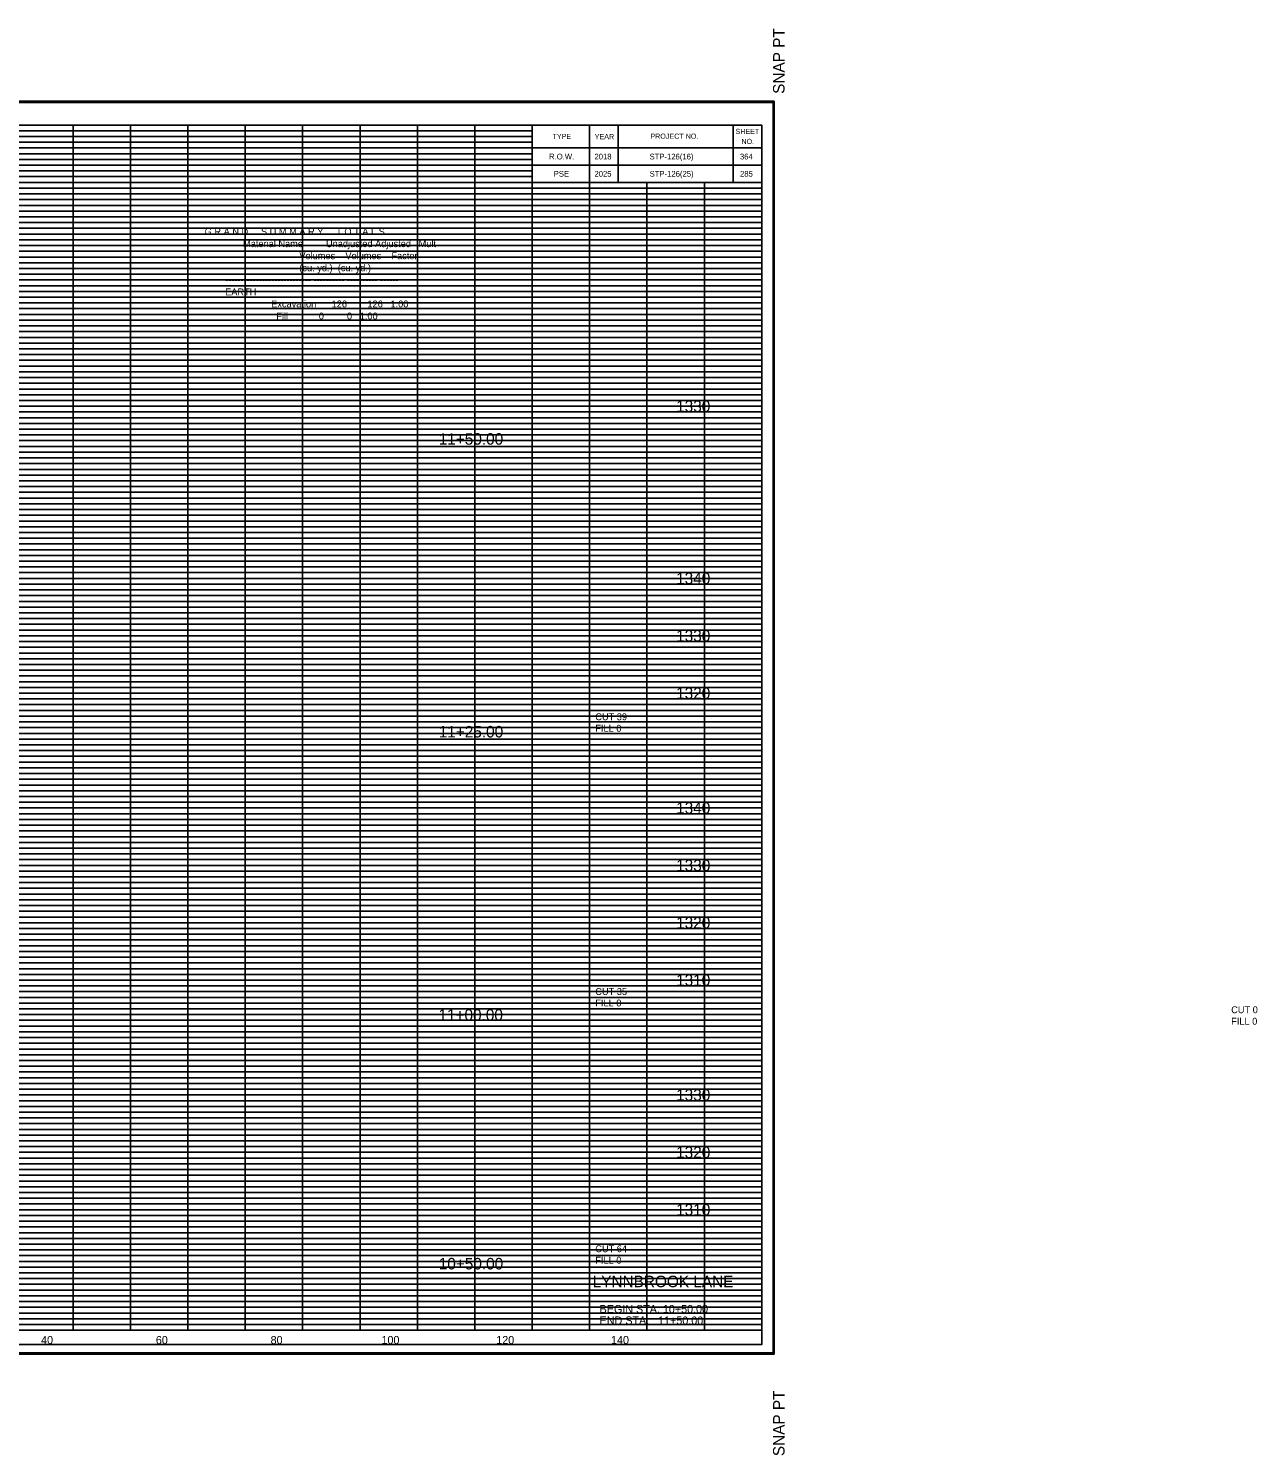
# Model space of a CAD drawing. Extents: x 980 to 1406, y 978 to 1227.
# Drawn here: x 1192.2 to 1406.4, y 978.2 to 1226.8 of the extents above; entities that cross this region are included whole.
import ezdxf

# ---------------------------------------------------------------- set-up
doc = ezdxf.new("R2010")
doc.units = 0
for name, color, linetype in [('DESIGN - SCRATCH - User 1', 7, 'Continuous'), ('DESIGN - SHEET - Corner Text', 7, 'Continuous'), ('DESIGN - SHEET - Light Grid', 7, 'Continuous'), ('DESIGN - SHEET - Linework', 7, 'Continuous'), ('DESIGN - SHEET - Plot Shape', 7, 'Continuous'), ('DESIGN - TYPICAL - Text', 7, 'Continuous')]:
    doc.layers.add(name, color=color, linetype=linetype)

# ---------------------------------------------------------------- blocks, each defined once
blk = doc.blocks.new('XSTSHT')
at = {"layer": 'DESIGN - SCRATCH - User 1'}
for p, q in [((28.5, 20.45), (28.5, 20.45)), ((29.24, 20.45), (29.24, 20.45)), ((30.49, 20.45), (30.49, 20.45)), ((31.74, 20.45), (31.74, 20.45)), ((28.5, 20.15), (28.5, 20.15)), ((29.24, 20.15), (29.24, 20.15)), ((30.49, 20.15), (30.49, 20.15)), ((31.74, 20.15), (31.74, 20.15))]:
    blk.add_line(p, q, dxfattribs=at)
at = {"layer": 'DESIGN - SHEET - Light Grid'}
for p, q in [((16, 20.9), (24, 20.9)), ((24, 20.9), (28, 20.9)), ((16, 20.8), (24, 20.8)), ((16, 20.7), (24, 20.7)), ((24, 20.8), (28, 20.8)), ((24, 20.7), (28, 20.7)), ((16, 20.6), (24, 20.6)), ((16, 20.5), (24, 20.5)), ((16, 20.4), (24, 20.4)), ((24, 20.6), (28, 20.6)), ((24, 20.5), (28, 20.5)), ((24, 20.4), (28, 20.4)), ((16, 20.3), (24, 20.3)), ((16, 20.2), (24, 20.2)), ((24, 20.3), (28, 20.3)), ((24, 20.2), (28, 20.2)), ((16, 20.1), (24, 20.1)), ((16, 19.9), (24, 19.9)), ((24, 20.1), (28, 20.1)), ((24, 19.9), (32, 19.9)), ((16, 19.8), (24, 19.8)), ((16, 19.7), (24, 19.7)), ((24, 19.8), (32, 19.8)), ((24, 19.7), (32, 19.7)), ((16, 19.6), (24, 19.6)), ((16, 19.5), (24, 19.5)), ((16, 19.4), (24, 19.4)), ((24, 19.6), (32, 19.6)), ((24, 19.5), (32, 19.5)), ((24, 19.4), (32, 19.4)), ((16, 19.3), (24, 19.3)), ((16, 19.2), (24, 19.2)), ((24, 19.3), (32, 19.3)), ((24, 19.2), (32, 19.2)), ((16, 19.1), (24, 19.1)), ((16, 18.9), (24, 18.9)), ((24, 19.1), (32, 19.1)), ((24, 18.9), (32, 18.9)), ((16, 18.8), (24, 18.8)), ((16, 18.7), (24, 18.7)), ((24, 18.8), (32, 18.8)), ((24, 18.7), (32, 18.7)), ((16, 18.6), (24, 18.6)), ((16, 18.5), (24, 18.5)), ((16, 18.4), (24, 18.4)), ((24, 18.6), (32, 18.6)), ((24, 18.5), (32, 18.5)), ((24, 18.4), (32, 18.4)), ((16, 18.3), (24, 18.3)), ((16, 18.2), (24, 18.2)), ((24, 18.3), (32, 18.3)), ((24, 18.2), (32, 18.2)), ((16, 18.1), (24, 18.1)), ((24, 18.1), (32, 18.1)), ((16, 17.9), (24, 17.9)), ((16, 17.8), (24, 17.8)), ((16, 17.7), (24, 17.7)), ((24, 17.9), (32, 17.9)), ((24, 17.8), (32, 17.8)), ((24, 17.7), (32, 17.7)), ((16, 17.6), (24, 17.6)), ((16, 17.5), (24, 17.5)), ((24, 17.6), (32, 17.6)), ((24, 17.5), (32, 17.5)), ((16, 17.4), (24, 17.4)), ((16, 17.3), (24, 17.3)), ((16, 17.2), (24, 17.2)), ((24, 17.4), (32, 17.4)), ((24, 17.3), (32, 17.3)), ((24, 17.2), (32, 17.2)), ((16, 17.1), (24, 17.1)), ((24, 17.1), (32, 17.1)), ((16, 16.9), (24, 16.9)), ((16, 16.8), (24, 16.8)), ((16, 16.7), (24, 16.7)), ((24, 16.9), (32, 16.9)), ((24, 16.8), (32, 16.8)), ((24, 16.7), (32, 16.7)), ((16, 16.6), (24, 16.6)), ((16, 16.5), (24, 16.5)), ((24, 16.6), (32, 16.6)), ((24, 16.5), (32, 16.5)), ((16, 16.4), (24, 16.4)), ((16, 16.3), (24, 16.3)), ((16, 16.2), (24, 16.2)), ((24, 16.4), (32, 16.4)), ((24, 16.3), (32, 16.3)), ((24, 16.2), (32, 16.2)), ((16, 16.1), (24, 16.1)), ((24, 16.1), (32, 16.1)), ((16, 15.9), (24, 15.9)), ((16, 15.8), (24, 15.8)), ((16, 15.7), (24, 15.7)), ((24, 15.9), (32, 15.9)), ((24, 15.8), (32, 15.8)), ((24, 15.7), (32, 15.7)), ((16, 15.6), (24, 15.6)), ((16, 15.5), (24, 15.5)), ((24, 15.6), (32, 15.6)), ((24, 15.5), (32, 15.5)), ((16, 15.4), (24, 15.4)), ((16, 15.3), (24, 15.3)), ((16, 15.2), (24, 15.2)), ((24, 15.4), (32, 15.4)), ((24, 15.3), (32, 15.3)), ((24, 15.2), (32, 15.2)), ((16, 15.1), (24, 15.1)), ((24, 15.1), (32, 15.1)), ((16, 14.9), (24, 14.9)), ((16, 14.8), (24, 14.8)), ((16, 14.7), (24, 14.7)), ((24, 14.9), (32, 14.9)), ((24, 14.8), (32, 14.8)), ((24, 14.7), (32, 14.7)), ((16, 14.6), (24, 14.6)), ((16, 14.5), (24, 14.5)), ((24, 14.6), (32, 14.6)), ((24, 14.5), (32, 14.5)), ((16, 14.4), (24, 14.4)), ((16, 14.3), (24, 14.3)), ((16, 14.2), (24, 14.2)), ((24, 14.4), (32, 14.4)), ((24, 14.3), (32, 14.3)), ((24, 14.2), (32, 14.2)), ((16, 14.1), (24, 14.1)), ((24, 14.1), (32, 14.1)), ((16, 13.9), (24, 13.9)), ((16, 13.8), (24, 13.8)), ((16, 13.7), (24, 13.7)), ((24, 13.9), (32, 13.9)), ((24, 13.8), (32, 13.8)), ((24, 13.7), (32, 13.7)), ((16, 13.6), (24, 13.6)), ((16, 13.5), (24, 13.5)), ((24, 13.6), (32, 13.6)), ((24, 13.5), (32, 13.5)), ((16, 13.4), (24, 13.4)), ((16, 13.3), (24, 13.3)), ((16, 13.2), (24, 13.2)), ((24, 13.4), (32, 13.4)), ((24, 13.3), (32, 13.3)), ((24, 13.2), (32, 13.2)), ((16, 13.1), (24, 13.1)), ((24, 13.1), (32, 13.1)), ((16, 12.9), (24, 12.9)), ((16, 12.8), (24, 12.8)), ((16, 12.7), (24, 12.7)), ((24, 12.9), (32, 12.9)), ((24, 12.8), (32, 12.8)), ((24, 12.7), (32, 12.7)), ((16, 12.6), (24, 12.6)), ((16, 12.5), (24, 12.5)), ((24, 12.6), (32, 12.6)), ((24, 12.5), (32, 12.5)), ((16, 12.4), (24, 12.4)), ((16, 12.3), (24, 12.3)), ((16, 12.2), (24, 12.2)), ((24, 12.4), (32, 12.4)), ((24, 12.3), (32, 12.3)), ((24, 12.2), (32, 12.2)), ((16, 12.1), (24, 12.1)), ((24, 12.1), (32, 12.1)), ((16, 11.9), (24, 11.9)), ((16, 11.8), (24, 11.8)), ((16, 11.7), (24, 11.7)), ((24, 11.9), (32, 11.9)), ((24, 11.8), (32, 11.8)), ((24, 11.7), (32, 11.7)), ((16, 11.6), (24, 11.6)), ((16, 11.5), (24, 11.5)), ((24, 11.6), (32, 11.6)), ((24, 11.5), (32, 11.5)), ((16, 11.4), (24, 11.4)), ((16, 11.3), (24, 11.3)), ((16, 11.2), (24, 11.2)), ((24, 11.4), (32, 11.4)), ((24, 11.3), (32, 11.3)), ((24, 11.2), (32, 11.2)), ((16, 11.1), (24, 11.1)), ((24, 11.1), (32, 11.1)), ((16, 10.9), (24, 10.9)), ((16, 10.8), (24, 10.8)), ((16, 10.7), (24, 10.7)), ((24, 10.9), (32, 10.9)), ((24, 10.8), (32, 10.8)), ((24, 10.7), (32, 10.7)), ((16, 10.6), (24, 10.6)), ((16, 10.5), (24, 10.5)), ((24, 10.6), (32, 10.6)), ((24, 10.5), (32, 10.5)), ((16, 10.4), (24, 10.4)), ((16, 10.3), (24, 10.3)), ((16, 10.2), (24, 10.2)), ((24, 10.4), (32, 10.4)), ((24, 10.3), (32, 10.3)), ((24, 10.2), (32, 10.2)), ((16, 10.1), (24, 10.1)), ((24, 10.1), (32, 10.1)), ((16, 9.9), (24, 9.9)), ((16, 9.8), (24, 9.8)), ((16, 9.7), (24, 9.7)), ((24, 9.9), (32, 9.9)), ((24, 9.8), (32, 9.8)), ((24, 9.7), (32, 9.7)), ((16, 9.6), (24, 9.6)), ((16, 9.5), (24, 9.5)), ((24, 9.6), (32, 9.6)), ((24, 9.5), (32, 9.5)), ((16, 9.4), (24, 9.4)), ((16, 9.3), (24, 9.3)), ((16, 9.2), (24, 9.2)), ((24, 9.4), (32, 9.4)), ((24, 9.3), (32, 9.3)), ((24, 9.2), (32, 9.2)), ((16, 9.1), (24, 9.1)), ((24, 9.1), (32, 9.1)), ((16, 8.9), (24, 8.9)), ((16, 8.8), (24, 8.8)), ((24, 8.9), (32, 8.9)), ((24, 8.8), (32, 8.8)), ((16, 8.7), (24, 8.7)), ((16, 8.6), (24, 8.6)), ((16, 8.5), (24, 8.5)), ((24, 8.7), (32, 8.7)), ((24, 8.6), (32, 8.6)), ((24, 8.5), (32, 8.5)), ((16, 8.4), (24, 8.4)), ((16, 8.3), (24, 8.3)), ((24, 8.4), (32, 8.4)), ((24, 8.3), (32, 8.3)), ((16, 8.2), (24, 8.2)), ((16, 8.1), (24, 8.1)), ((24, 8.2), (32, 8.2)), ((24, 8.1), (32, 8.1)), ((16, 7.9), (24, 7.9)), ((16, 7.8), (24, 7.8)), ((24, 7.9), (32, 7.9)), ((24, 7.8), (32, 7.8)), ((16, 7.7), (24, 7.7)), ((16, 7.6), (24, 7.6)), ((16, 7.5), (24, 7.5)), ((24, 7.7), (32, 7.7)), ((24, 7.6), (32, 7.6)), ((24, 7.5), (32, 7.5)), ((16, 7.4), (24, 7.4)), ((16, 7.3), (24, 7.3)), ((24, 7.4), (32, 7.4)), ((24, 7.3), (32, 7.3)), ((16, 7.2), (24, 7.2)), ((16, 7.1), (24, 7.1)), ((24, 7.2), (32, 7.2)), ((24, 7.1), (32, 7.1)), ((16, 6.9), (24, 6.9)), ((16, 6.8), (24, 6.8)), ((24, 6.9), (32, 6.9)), ((24, 6.8), (32, 6.8)), ((16, 6.7), (24, 6.7)), ((16, 6.6), (24, 6.6)), ((16, 6.5), (24, 6.5)), ((24, 6.7), (32, 6.7)), ((24, 6.6), (32, 6.6)), ((24, 6.5), (32, 6.5)), ((16, 6.4), (24, 6.4)), ((16, 6.3), (24, 6.3)), ((24, 6.4), (32, 6.4)), ((24, 6.3), (32, 6.3)), ((16, 6.2), (24, 6.2)), ((16, 6.1), (24, 6.1)), ((24, 6.2), (32, 6.2)), ((24, 6.1), (32, 6.1)), ((16, 5.9), (24, 5.9)), ((16, 5.8), (24, 5.8)), ((24, 5.9), (32, 5.9)), ((24, 5.8), (32, 5.8)), ((16, 5.7), (24, 5.7)), ((16, 5.6), (24, 5.6)), ((16, 5.5), (24, 5.5)), ((24, 5.7), (32, 5.7)), ((24, 5.6), (32, 5.6)), ((24, 5.5), (32, 5.5)), ((16, 5.4), (24, 5.4)), ((16, 5.3), (24, 5.3)), ((24, 5.4), (32, 5.4)), ((24, 5.3), (32, 5.3)), ((16, 5.2), (24, 5.2)), ((16, 5.1), (24, 5.1)), ((24, 5.2), (32, 5.2)), ((24, 5.1), (32, 5.1)), ((16, 4.9), (24, 4.9)), ((16, 4.8), (24, 4.8)), ((24, 4.9), (32, 4.9)), ((24, 4.8), (32, 4.8)), ((16, 4.7), (24, 4.7)), ((16, 4.6), (24, 4.6)), ((16, 4.5), (24, 4.5)), ((24, 4.7), (32, 4.7)), ((24, 4.6), (32, 4.6)), ((24, 4.5), (32, 4.5)), ((16, 4.4), (24, 4.4)), ((16, 4.3), (24, 4.3)), ((24, 4.4), (32, 4.4)), ((24, 4.3), (32, 4.3)), ((16, 4.2), (24, 4.2)), ((16, 4.1), (24, 4.1)), ((24, 4.2), (32, 4.2)), ((24, 4.1), (32, 4.1)), ((16, 3.9), (24, 3.9)), ((16, 3.8), (24, 3.8)), ((24, 3.9), (32, 3.9)), ((24, 3.8), (32, 3.8)), ((16, 3.7), (24, 3.7)), ((16, 3.6), (24, 3.6)), ((16, 3.5), (24, 3.5)), ((24, 3.7), (32, 3.7)), ((24, 3.6), (32, 3.6)), ((24, 3.5), (32, 3.5)), ((16, 3.4), (24, 3.4)), ((16, 3.3), (24, 3.3)), ((24, 3.4), (32, 3.4)), ((24, 3.3), (32, 3.3)), ((16, 3.2), (24, 3.2)), ((16, 3.1), (24, 3.1)), ((24, 3.2), (32, 3.2)), ((24, 3.1), (32, 3.1)), ((16, 2.9), (24, 2.9)), ((16, 2.8), (24, 2.8)), ((24, 2.9), (32, 2.9)), ((24, 2.8), (32, 2.8)), ((16, 2.7), (24, 2.7)), ((16, 2.6), (24, 2.6)), ((16, 2.5), (24, 2.5)), ((24, 2.7), (32, 2.7)), ((24, 2.6), (32, 2.6)), ((24, 2.5), (32, 2.5)), ((16, 2.4), (24, 2.4)), ((16, 2.3), (24, 2.3)), ((24, 2.4), (32, 2.4)), ((24, 2.3), (32, 2.3)), ((16, 2.2), (24, 2.2)), ((16, 2.1), (24, 2.1)), ((24, 2.2), (32, 2.2)), ((24, 2.1), (32, 2.1)), ((16, 1.9), (24, 1.9)), ((16, 1.8), (24, 1.8)), ((24, 1.9), (32, 1.9)), ((24, 1.8), (32, 1.8)), ((16, 1.7), (24, 1.7)), ((16, 1.6), (24, 1.6)), ((16, 1.5), (24, 1.5)), ((24, 1.7), (32, 1.7)), ((24, 1.6), (32, 1.6)), ((24, 1.5), (32, 1.5)), ((16, 1.4), (24, 1.4)), ((16, 1.3), (24, 1.3)), ((24, 1.4), (32, 1.4)), ((24, 1.3), (32, 1.3)), ((16, 1.2), (24, 1.2)), ((16, 1.1), (24, 1.1)), ((24, 1.2), (32, 1.2)), ((24, 1.1), (32, 1.1)), ((16, 0.9), (24, 0.9)), ((16, 0.8), (24, 0.8)), ((24, 0.9), (32, 0.9)), ((24, 0.8), (32, 0.8)), ((16, 0.7), (24, 0.7)), ((16, 0.6), (24, 0.6)), ((16, 0.5), (24, 0.5)), ((24, 0.7), (32, 0.7)), ((24, 0.6), (32, 0.6)), ((24, 0.5), (32, 0.5)), ((16, 0.4), (24, 0.4)), ((16, 0.3), (24, 0.3)), ((24, 0.4), (32, 0.4)), ((24, 0.3), (32, 0.3)), ((16, 0.2), (24, 0.2)), ((16, 0.1), (24, 0.1)), ((24, 0.2), (32, 0.2)), ((24, 0.1), (32, 0.1))]:
    blk.add_line(p, q, dxfattribs=at)
at = {"layer": 'DESIGN - SHEET - Linework'}
for p, q in [((-1.823, 21.414), (32.217, 21.414)), ((32.217, 21.414), (32.217, -0.414)), ((20, 0), (20, 21)), ((21, 0), (21, 21)), ((22, 0), (22, 21)), ((23, 0), (23, 21)), ((24, 0), (24, 21)), ((25, 0), (25, 21)), ((26, 0), (26, 21)), ((27, 0), (27, 21)), ((0, 20), (28, 20)), ((28, 0), (28, 20)), ((29, 0), (29, 20)), ((30, 0), (30, 20)), ((31, 0), (31, 20)), ((0, 19), (32, 19)), ((0, 18), (32, 18)), ((0, 17), (32, 17)), ((0, 16), (32, 16)), ((0, 15), (32, 15)), ((0, 14), (32, 14)), ((0, 13), (32, 13)), ((0, 12), (32, 12)), ((0, 11), (32, 11)), ((0, 10), (32, 10)), ((0, 9), (32, 9)), ((0, 8), (32, 8)), ((0, 7), (32, 7)), ((0, 6), (32, 6)), ((0, 5), (32, 5)), ((0, 4), (32, 4)), ((0, 3), (32, 3)), ((0, 2), (32, 2)), ((0, 1), (32, 1)), ((-1.823, -0.414), (32.217, -0.414))]:
    blk.add_line(p, q, dxfattribs=at)
for points in [[(0, 21), (0, 0), (32, 0), (32, 21), (0, 21)], [(28, 21), (28, 20), (32, 20), (32, 21), (31.5, 21), (31.5, 20), (29.5, 20), (29.5, 21), (29, 21), (29, 20), (32, 20), (28, 20), (28, 20.3), (32, 20.3), (32, 20.6), (28, 20.6)]]:
    blk.add_lwpolyline(points, dxfattribs=at)
at = {"layer": 'DESIGN - SHEET - Plot Shape'}
for points in [[(-1.803, 21.394), (32.197, 21.394), (32.197, -0.394), (-1.803, -0.394)], [(-0.85, 21), (32, 21), (32, -0.25), (-0.85, -0.25)]]:
    blk.add_lwpolyline(points, close=True, dxfattribs=at)
at = {"layer": 'DESIGN - SHEET - Corner Text'}
for s, p in [('  SNAP PT', (32.397, 21.394)), ('SNAP PT  ', (32.397, -2.194))]:
    blk.add_text(s, height=0.2, rotation=90, dxfattribs=at).set_placement(p)
for s, p in [('SHEET', (31.543, 20.843)), ('TYPE', (28.354, 20.756)), ('YEAR', (29.09, 20.752)), ('PROJECT NO.', (30.06, 20.76)), ('NO.', (31.646, 20.669))]:
    blk.add_text(s, height=0.09, dxfattribs=at).set_placement(p)

msp = doc.modelspace()

# ---------------------------------------------------------------- linework, layer by layer
at = {"layer": 'DESIGN - SHEET - Plot Shape'}
msp.add_lwpolyline([(991.5, 997.5), (1320, 997.5), (1320, 1210), (991.5, 1210)], close=True, dxfattribs=at)

# ---------------------------------------------------------------- block references
at = {"layer": 'DESIGN - TYPICAL - Text', "xscale": 10, "yscale": 10}
msp.add_blockref('XSTSHT', (1000, 1000), dxfattribs=at)

# ---------------------------------------------------------------- texts
at = {"layer": 'DESIGN - SHEET - Corner Text'}
for s, height, p in [('R.O.W.', 1, (1282.94, 1204)), ('2018', 1, (1290.85, 1204)), ('STP-126(16)', 1, (1300.45, 1204)), ('364', 1, (1316.2, 1204)), ('PSE', 1, (1283.75, 1201)), ('2025', 1, (1290.85, 1201)), ('STP-126(25)', 1, (1300.47, 1201)), ('285', 1, (1316.22, 1201)), ('LYNNBROOK LANE', 2, (1290.55, 1007.5)), ('BEGIN STA. 10+50.00', 1.4, (1291.75, 1003)), ('END STA.   11+50.00', 1.4, (1291.75, 1001))]:
    msp.add_text(s, height=height, dxfattribs=at).set_placement(p)
at = {"layer": 'DESIGN - TYPICAL - Text'}
for s, height, p in [('G R A N D     S U M M A R Y     T O T A L S', 1.2, (1222.93, 1190.82)), ('               Material Name         Unadjusted Adjusted   Mult', 1.2, (1222.93, 1188.72)), ('                                     Volumes    Volumes    Factor', 1.2, (1222.93, 1186.62)), ('                                     (cu. yd.)  (cu. yd.)', 1.2, (1222.93, 1184.52)), ('        ---------------------------- ---------- ---------- ------', 1.2, (1222.93, 1182.42)), ('        EARTH', 1.2, (1222.93, 1180.32)), ('                          Excavation      126        126   1.00', 1.2, (1222.93, 1178.22)), ('                            Fill            0         0   1.00', 1.2, (1222.93, 1176.12)), ('     1330     ', 2, (1301.37, 1160)), ('     11+50.00     ', 2, (1260, 1154.3)), ('     1340     ', 2, (1301.37, 1130)), ('     1330     ', 2, (1301.37, 1120)), ('     1320     ', 2, (1301.37, 1110)), ('CUT 39', 1.2, (1291, 1106.29)), ('     11+25.00     ', 2, (1260, 1103.29)), ('FILL 0', 1.2, (1291, 1104.29)), ('     1340     ', 2, (1301.37, 1090)), ('     1330     ', 2, (1301.37, 1080)), ('     1320     ', 2, (1301.37, 1070)), ('     1310     ', 2, (1301.37, 1060)), ('CUT 35', 1.2, (1291, 1058.42)), ('FILL 0', 1.2, (1291, 1056.42)), ('     11+00.00     ', 2, (1259.95, 1053.94)), ('CUT 0', 1.2, (1401.81, 1055.24)), ('FILL 0', 1.2, (1401.81, 1053.24)), ('     1330     ', 2, (1301.37, 1040)), ('     1320     ', 2, (1301.37, 1030)), ('     1310     ', 2, (1301.37, 1020)), ('CUT 64', 1.2, (1291, 1013.6)), ('     10+50.00     ', 2, (1260, 1010.6)), ('FILL 0', 1.2, (1291, 1011.6)), ('     40     ', 1.4, (1191.82, 997.6)), ('     60     ', 1.4, (1211.82, 997.6)), ('     80     ', 1.4, (1231.82, 997.6)), ('     100     ', 1.4, (1251.14, 997.6)), ('     120     ', 1.4, (1271.14, 997.6)), ('     140     ', 1.4, (1291.14, 997.6))]:
    msp.add_text(s, height=height, dxfattribs=at).set_placement(p)

doc.saveas('drawing.dxf')
